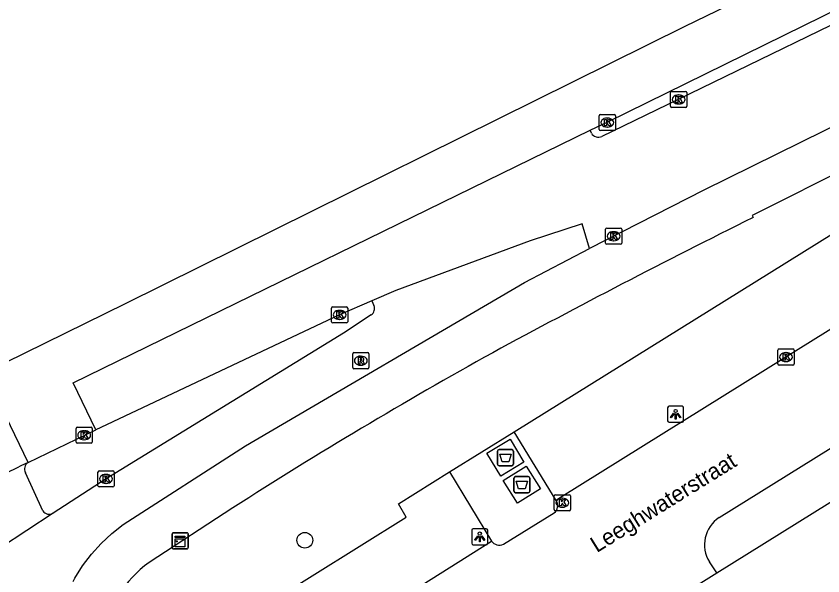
# Model space of a CAD drawing. Extents: x 159888 to 160757, y 384031 to 384746.
# Drawn here: x 160015.4 to 160065.5, y 384569.7 to 384604.4 of the extents above; entities that cross this region are included whole.
import ezdxf

# ---------------------------------------------------------------- set-up
doc = ezdxf.new("R2010")
doc.units = 0
for name, color, linetype in [('IMGEO_Afval_apart_plaats', 7, 'Continuous'), ('IMGEO_Boom', 7, 'Continuous'), ('IMGEO_Fietspad_gesloten', 7, 'Continuous'), ('IMGEO_Kast', 7, 'Continuous'), ('IMGEO_Kolk', 7, 'Continuous'), ('IMGEO_Lichtpunt', 7, 'Continuous'), ('IMGEO_Openbare_ruimte_label', 7, 'Continuous'), ('IMGEO_Pand', 7, 'Continuous'), ('IMGEO_Parkeervlak_open', 7, 'Continuous'), ('IMGEO_Rijbaan_lokaal_open', 7, 'Continuous'), ('IMGEO_Rijbaan_regionaal_gesloten', 7, 'Continuous'), ('IMGEO_Rioolput', 7, 'Continuous'), ('IMGEO_Voetpad_gesloten', 7, 'Continuous'), ('IMGEO_Voetpad_open', 7, 'Continuous')]:
    doc.layers.add(name, color=color, linetype=linetype)

msp = doc.modelspace()

# ---------------------------------------------------------------- linework, layer by layer
at = {"layer": 'IMGEO_Afval_apart_plaats'}
for p, q in [((160045.285, 384576.603), (160045.285, 384577.403)), ((160045.285, 384577.403), (160045.285, 384576.603)), ((160045.385, 384577.503), (160046.175, 384577.503)), ((160046.175, 384577.503), (160045.385, 384577.503)), ((160046.275, 384577.403), (160046.275, 384576.603)), ((160046.275, 384576.603), (160046.275, 384577.403)), ((160046.175, 384576.503), (160045.385, 384576.503)), ((160045.385, 384576.503), (160046.175, 384576.503)), ((160046.309, 384574.927), (160046.309, 384575.727)), ((160046.309, 384575.727), (160046.309, 384574.927)), ((160046.409, 384575.827), (160047.199, 384575.827)), ((160047.199, 384575.827), (160046.409, 384575.827)), ((160047.299, 384575.727), (160047.299, 384574.927)), ((160047.299, 384574.927), (160047.299, 384575.727)), ((160047.199, 384574.827), (160046.409, 384574.827)), ((160046.409, 384574.827), (160047.199, 384574.827))]:
    msp.add_line(p, q, dxfattribs=at)
for points in [[(160045.428, 384577.217), (160046.132, 384577.217), (160045.983, 384576.747), (160045.577, 384576.747), (160045.428, 384577.217)], [(160046.452, 384575.541), (160047.156, 384575.541), (160047.007, 384575.071), (160046.601, 384575.071), (160046.452, 384575.541)]]:
    msp.add_lwpolyline(points, dxfattribs=at)
for centre, start, end in [((160045.385, 384577.403), 90, 180), ((160045.385, 384577.403), 90, 180), ((160046.175, 384577.403), 0, 90), ((160046.175, 384577.403), 360, 90), ((160045.385, 384576.603), 180, 270), ((160045.385, 384576.603), 180, 270), ((160046.175, 384576.603), 270, 0), ((160046.175, 384576.603), 270, 0), ((160046.409, 384575.727), 90, 180), ((160046.409, 384575.727), 90, 180), ((160047.199, 384575.727), 0, 90), ((160047.199, 384575.727), 360, 90), ((160046.409, 384574.927), 180, 270), ((160046.409, 384574.927), 180, 270), ((160047.199, 384574.927), 270, 0), ((160047.199, 384574.927), 270, 0)]:
    msp.add_arc(centre, 0.1, start, end, dxfattribs=at)
at = {"layer": 'IMGEO_Boom'}
msp.add_circle((160033.317, 384571.876), 0.489, dxfattribs=at)
at = {"layer": 'IMGEO_Fietspad_gesloten'}
for points in [[(160018.927, 384569.315), (160019.03, 384569.518), (160019.508, 384570.287), (160020.053, 384571.009), (160020.659, 384571.68), (160021.324, 384572.294), (160022.04, 384572.846), (160029.623, 384577.749), (160046.967, 384587.883), (160051.012, 384589.991)], [(160037.477, 384586.735), (160037.608, 384586.46)], [(160037.444, 384585.867), (160035.722, 384584.738), (160020.966, 384575.687), (160017.679, 384573.562)], [(160017.679, 384573.562), (160014.403, 384571.399)]]:
    msp.add_lwpolyline(points, dxfattribs=at)
msp.add_arc((160037.168, 384586.262), 0.482, 304.8999, 24.1814, dxfattribs=at)
at = {"layer": 'IMGEO_Kast'}
for p, q in [((160025.07, 384571.421), (160025.07, 384572.262)), ((160025.07, 384572.262), (160025.07, 384571.421)), ((160025.145, 384572.346), (160025.986, 384572.346)), ((160025.986, 384572.346), (160025.145, 384572.346)), ((160026.07, 384572.271), (160026.07, 384571.43)), ((160026.07, 384571.43), (160026.07, 384572.271)), ((160025.995, 384571.346), (160025.154, 384571.346)), ((160025.154, 384571.346), (160025.995, 384571.346))]:
    msp.add_line(p, q, dxfattribs=at)
for points in [[(160025.265, 384572.136), (160025.865, 384572.136), (160025.865, 384572.051), (160025.265, 384572.051), (160025.265, 384572.136)], [(160025.265, 384571.961), (160025.865, 384571.961), (160025.865, 384571.472), (160025.265, 384571.472), (160025.265, 384571.961)]]:
    msp.add_lwpolyline(points, dxfattribs=at)
msp.add_circle((160025.349, 384571.81), 0.0377, dxfattribs=at)
for centre, start, end in [((160025.148, 384572.268), 92.4484, 184.2845), ((160025.148, 384572.268), 92.4484, 184.2845), ((160025.992, 384572.268), 2.4484, 94.2845), ((160025.992, 384572.268), 2.4484, 94.2845), ((160025.148, 384571.424), 182.4484, 274.2845), ((160025.148, 384571.424), 182.4484, 274.2845), ((160025.992, 384571.424), 272.4484, 4.2845), ((160025.992, 384571.424), 272.4484, 4.2845)]:
    msp.add_arc(centre, 0.0779, start, end, dxfattribs=at)
at = {"layer": 'IMGEO_Kolk'}
for p, q in [((160056.04, 384598.822), (160056.04, 384599.674)), ((160056.115, 384599.748), (160056.967, 384599.748)), ((160057.041, 384599.674), (160057.041, 384598.822)), ((160056.528, 384599.528), (160056.553, 384599.528)), ((160056.967, 384598.748), (160056.115, 384598.748)), ((160056.551, 384598.968), (160056.526, 384598.968)), ((160051.608, 384597.387), (160051.608, 384598.239)), ((160051.683, 384598.313), (160052.535, 384598.313)), ((160052.609, 384598.239), (160052.609, 384597.387)), ((160052.096, 384598.093), (160052.121, 384598.093)), ((160052.535, 384597.313), (160051.683, 384597.313)), ((160052.119, 384597.533), (160052.094, 384597.533)), ((160052.002, 384590.332), (160052.002, 384591.184)), ((160052.077, 384591.258), (160052.929, 384591.258)), ((160053.003, 384591.184), (160053.003, 384590.332)), ((160052.49, 384591.038), (160052.515, 384591.038)), ((160052.929, 384590.258), (160052.077, 384590.258)), ((160052.513, 384590.478), (160052.488, 384590.478)), ((160034.977, 384585.446), (160034.977, 384586.298)), ((160035.052, 384586.372), (160035.904, 384586.372)), ((160035.465, 384586.152), (160035.49, 384586.152)), ((160035.978, 384586.298), (160035.978, 384585.446)), ((160035.488, 384585.592), (160035.463, 384585.592)), ((160035.904, 384585.372), (160035.052, 384585.372)), ((160062.709, 384582.827), (160062.709, 384583.679)), ((160062.784, 384583.753), (160063.636, 384583.753)), ((160063.71, 384583.679), (160063.71, 384582.827)), ((160063.197, 384583.533), (160063.222, 384583.533)), ((160063.636, 384582.753), (160062.784, 384582.753)), ((160063.22, 384582.973), (160063.195, 384582.973)), ((160019.106, 384577.974), (160019.106, 384578.826)), ((160019.181, 384578.9), (160020.033, 384578.9)), ((160019.594, 384578.68), (160019.619, 384578.68)), ((160020.107, 384578.826), (160020.107, 384577.974)), ((160019.617, 384578.12), (160019.592, 384578.12)), ((160020.033, 384577.9), (160019.181, 384577.9)), ((160020.465, 384575.261), (160020.465, 384576.113)), ((160020.54, 384576.187), (160021.392, 384576.187)), ((160021.466, 384576.113), (160021.466, 384575.261)), ((160020.953, 384575.967), (160020.978, 384575.967)), ((160021.392, 384575.187), (160020.54, 384575.187)), ((160020.976, 384575.407), (160020.951, 384575.407)), ((160048.813, 384573.78), (160048.813, 384574.632)), ((160048.888, 384574.706), (160049.74, 384574.706)), ((160049.814, 384574.632), (160049.814, 384573.78)), ((160049.301, 384574.486), (160049.326, 384574.486)), ((160049.74, 384573.706), (160048.888, 384573.706)), ((160049.324, 384573.926), (160049.299, 384573.926))]:
    msp.add_line(p, q, dxfattribs=at)
for points in [[(160056.04, 384598.822), (160056.04, 384599.674)], [(160056.115, 384599.748), (160056.967, 384599.748)], [(160057.041, 384599.674), (160057.041, 384598.822)], [(160056.361, 384599.448), (160056.484, 384599.448), (160056.484, 384599.297), (160056.614, 384599.448), (160056.778, 384599.448), (160056.632, 384599.297), (160056.785, 384599.048), (160056.633, 384599.048), (160056.548, 384599.212), (160056.484, 384599.145), (160056.484, 384599.048), (160056.361, 384599.048), (160056.361, 384599.448)], [(160056.967, 384598.748), (160056.115, 384598.748)], [(160051.608, 384597.387), (160051.608, 384598.239)], [(160051.683, 384598.313), (160052.535, 384598.313)], [(160052.609, 384598.239), (160052.609, 384597.387)], [(160051.929, 384598.013), (160052.052, 384598.013), (160052.052, 384597.862), (160052.182, 384598.013), (160052.346, 384598.013), (160052.2, 384597.862), (160052.353, 384597.613), (160052.201, 384597.613), (160052.116, 384597.777), (160052.052, 384597.71), (160052.052, 384597.613), (160051.929, 384597.613), (160051.929, 384598.013)], [(160052.535, 384597.313), (160051.683, 384597.313)], [(160052.002, 384590.332), (160052.002, 384591.184)], [(160052.077, 384591.258), (160052.929, 384591.258)], [(160053.003, 384591.184), (160053.003, 384590.332)], [(160052.323, 384590.958), (160052.446, 384590.958), (160052.446, 384590.807), (160052.576, 384590.958), (160052.74, 384590.958), (160052.594, 384590.807), (160052.747, 384590.558), (160052.595, 384590.558), (160052.51, 384590.722), (160052.446, 384590.655), (160052.446, 384590.558), (160052.323, 384590.558), (160052.323, 384590.958)], [(160052.929, 384590.258), (160052.077, 384590.258)], [(160034.977, 384585.446), (160034.977, 384586.298)], [(160035.052, 384586.372), (160035.904, 384586.372)], [(160035.978, 384586.298), (160035.978, 384585.446)], [(160035.298, 384586.072), (160035.421, 384586.072), (160035.421, 384585.921), (160035.551, 384586.072), (160035.715, 384586.072), (160035.569, 384585.921), (160035.722, 384585.672), (160035.57, 384585.672), (160035.485, 384585.836), (160035.421, 384585.769), (160035.421, 384585.672), (160035.298, 384585.672), (160035.298, 384586.072)], [(160035.904, 384585.372), (160035.052, 384585.372)], [(160062.709, 384582.827), (160062.709, 384583.679)], [(160062.784, 384583.753), (160063.636, 384583.753)], [(160063.71, 384583.679), (160063.71, 384582.827)], [(160063.03, 384583.453), (160063.153, 384583.453), (160063.153, 384583.302), (160063.283, 384583.453), (160063.447, 384583.453), (160063.301, 384583.302), (160063.454, 384583.053), (160063.302, 384583.053), (160063.217, 384583.217), (160063.153, 384583.15), (160063.153, 384583.053), (160063.03, 384583.053), (160063.03, 384583.453)], [(160063.636, 384582.753), (160062.784, 384582.753)], [(160019.106, 384577.974), (160019.106, 384578.826)], [(160019.181, 384578.9), (160020.033, 384578.9)], [(160019.427, 384578.6), (160019.55, 384578.6), (160019.55, 384578.449), (160019.68, 384578.6), (160019.844, 384578.6), (160019.698, 384578.449), (160019.851, 384578.2), (160019.699, 384578.2), (160019.614, 384578.364), (160019.55, 384578.297), (160019.55, 384578.2), (160019.427, 384578.2), (160019.427, 384578.6)], [(160020.107, 384578.826), (160020.107, 384577.974)], [(160020.033, 384577.9), (160019.181, 384577.9)], [(160020.465, 384575.261), (160020.465, 384576.113)], [(160020.54, 384576.187), (160021.392, 384576.187)], [(160021.466, 384576.113), (160021.466, 384575.261)], [(160020.786, 384575.887), (160020.909, 384575.887), (160020.909, 384575.736), (160021.039, 384575.887), (160021.203, 384575.887), (160021.057, 384575.736), (160021.21, 384575.487), (160021.058, 384575.487), (160020.973, 384575.651), (160020.909, 384575.584), (160020.909, 384575.487), (160020.786, 384575.487), (160020.786, 384575.887)], [(160021.392, 384575.187), (160020.54, 384575.187)], [(160048.813, 384573.78), (160048.813, 384574.632)], [(160048.888, 384574.706), (160049.74, 384574.706)], [(160049.814, 384574.632), (160049.814, 384573.78)], [(160049.134, 384574.406), (160049.257, 384574.406), (160049.257, 384574.255), (160049.387, 384574.406), (160049.551, 384574.406), (160049.405, 384574.255), (160049.558, 384574.006), (160049.406, 384574.006), (160049.321, 384574.17), (160049.257, 384574.103), (160049.257, 384574.006), (160049.134, 384574.006), (160049.134, 384574.406)], [(160049.74, 384573.706), (160048.888, 384573.706)]]:
    msp.add_lwpolyline(points, dxfattribs=at)
for centre, start, end in [((160056.117, 384599.672), 91.552, 178.448), ((160056.117, 384599.672), 91.552, 178.448), ((160056.965, 384599.672), 1.552, 88.448), ((160056.965, 384599.672), 1.552, 88.448), ((160056.117, 384598.824), 181.552, 268.448), ((160056.117, 384598.824), 181.552, 268.448), ((160056.965, 384598.824), 271.552, 358.448), ((160056.965, 384598.824), 271.552, 358.448), ((160051.685, 384598.237), 91.552, 178.448), ((160051.685, 384598.237), 91.552, 178.448), ((160052.533, 384598.237), 1.552, 88.448), ((160052.533, 384598.237), 1.552, 88.448), ((160051.685, 384597.389), 181.552, 268.448), ((160051.685, 384597.389), 181.552, 268.448), ((160052.533, 384597.389), 271.552, 358.448), ((160052.533, 384597.389), 271.552, 358.448), ((160052.079, 384591.182), 91.552, 178.448), ((160052.079, 384591.182), 91.552, 178.448), ((160052.927, 384591.182), 1.552, 88.448), ((160052.927, 384591.182), 1.552, 88.448), ((160052.079, 384590.334), 181.552, 268.448), ((160052.079, 384590.334), 181.552, 268.448), ((160052.927, 384590.334), 271.552, 358.448), ((160052.927, 384590.334), 271.552, 358.448), ((160035.054, 384586.296), 91.552, 178.448), ((160035.054, 384586.296), 91.552, 178.448), ((160035.902, 384586.296), 1.552, 88.448), ((160035.902, 384586.296), 1.552, 88.448), ((160035.054, 384585.448), 181.552, 268.448), ((160035.054, 384585.448), 181.552, 268.448), ((160035.902, 384585.448), 271.552, 358.448), ((160035.902, 384585.448), 271.552, 358.448), ((160062.786, 384583.677), 91.552, 178.448), ((160062.786, 384583.677), 91.552, 178.448), ((160063.634, 384583.677), 1.552, 88.448), ((160063.634, 384583.677), 1.552, 88.448), ((160062.786, 384582.829), 181.552, 268.448), ((160062.786, 384582.829), 181.552, 268.448), ((160063.634, 384582.829), 271.552, 358.448), ((160063.634, 384582.829), 271.552, 358.448), ((160019.183, 384578.824), 91.552, 178.448), ((160019.183, 384578.824), 91.552, 178.448), ((160020.031, 384578.824), 1.552, 88.448), ((160020.031, 384578.824), 1.552, 88.448), ((160019.183, 384577.976), 181.552, 268.448), ((160019.183, 384577.976), 181.552, 268.448), ((160020.031, 384577.976), 271.552, 358.448), ((160020.031, 384577.976), 271.552, 358.448), ((160020.542, 384576.111), 91.552, 178.448), ((160020.542, 384576.111), 91.552, 178.448), ((160021.39, 384576.111), 1.552, 88.448), ((160021.39, 384576.111), 1.552, 88.448), ((160020.542, 384575.263), 181.552, 268.448), ((160020.542, 384575.263), 181.552, 268.448), ((160021.39, 384575.263), 271.552, 358.448), ((160021.39, 384575.263), 271.552, 358.448), ((160048.89, 384574.63), 91.552, 178.448), ((160048.89, 384574.63), 91.552, 178.448), ((160049.738, 384574.63), 1.552, 88.448), ((160049.738, 384574.63), 1.552, 88.448), ((160048.89, 384573.782), 181.552, 268.448), ((160048.89, 384573.782), 181.552, 268.448), ((160049.738, 384573.782), 271.552, 358.448), ((160049.738, 384573.782), 271.552, 358.448)]:
    msp.add_arc(centre, 0.0765, start, end, dxfattribs=at)
for centre, major_axis, ratio, start_param, end_param in [((160056.527, 384599.248), (-0.387, 0.002), 0.722429, 4.712389, 7.853982), ((160056.552, 384599.248), (-0.39, 0.002), 0.717154, 1.570796, 4.712389), ((160052.095, 384597.813), (-0.387, 0.002), 0.722429, 4.712389, 7.853982), ((160052.12, 384597.813), (-0.39, 0.002), 0.717154, 1.570796, 4.712389), ((160052.489, 384590.758), (-0.387, 0.002), 0.722429, 4.712389, 7.853982), ((160052.514, 384590.758), (-0.39, 0.002), 0.717154, 1.570796, 4.712389), ((160035.464, 384585.872), (-0.387, 0.002), 0.722429, 4.712389, 7.853982), ((160035.489, 384585.872), (-0.39, 0.002), 0.717154, 1.570796, 4.712389), ((160063.196, 384583.253), (-0.387, 0.002), 0.722429, 4.712389, 7.853982), ((160063.221, 384583.253), (-0.39, 0.002), 0.717154, 1.570796, 4.712389), ((160019.593, 384578.4), (-0.387, 0.002), 0.722429, 4.712389, 7.853982), ((160019.618, 384578.4), (-0.39, 0.002), 0.717154, 1.570796, 4.712389), ((160020.952, 384575.687), (-0.387, 0.002), 0.722429, 4.712389, 7.853982), ((160020.977, 384575.687), (-0.39, 0.002), 0.717154, 1.570796, 4.712389), ((160049.3, 384574.206), (-0.387, 0.002), 0.722429, 4.712389, 7.853982), ((160049.325, 384574.206), (-0.39, 0.002), 0.717154, 1.570796, 4.712389)]:
    msp.add_ellipse(centre, major_axis=major_axis, ratio=ratio, start_param=start_param, end_param=end_param, dxfattribs=at)
at = {"layer": 'IMGEO_Lichtpunt'}
for p, q in [((160055.856, 384580.101), (160055.856, 384579.294)), ((160055.856, 384580.101), (160055.856, 384579.294)), ((160056.758, 384580.196), (160055.95, 384580.196)), ((160056.758, 384580.196), (160055.95, 384580.196)), ((160056.852, 384579.294), (160056.852, 384580.101)), ((160056.852, 384579.294), (160056.852, 384580.101)), ((160055.95, 384579.2), (160056.758, 384579.2)), ((160055.95, 384579.2), (160056.758, 384579.2)), ((160044.586, 384572.588), (160043.778, 384572.588)), ((160044.586, 384572.588), (160043.778, 384572.588)), ((160043.684, 384572.493), (160043.684, 384571.686)), ((160043.684, 384572.493), (160043.684, 384571.686)), ((160044.68, 384571.686), (160044.68, 384572.493)), ((160044.68, 384571.686), (160044.68, 384572.493)), ((160043.778, 384571.592), (160044.586, 384571.592)), ((160043.778, 384571.592), (160044.586, 384571.592))]:
    msp.add_line(p, q, dxfattribs=at)
for points in [[(160056.23, 384579.765), (160056.269, 384579.737), (160056.081, 384579.475), (160056.043, 384579.502), (160056.23, 384579.765)], [(160056.332, 384579.717), (160056.379, 384579.717), (160056.379, 384579.395), (160056.332, 384579.395), (160056.332, 384579.717)], [(160056.442, 384579.737), (160056.48, 384579.764), (160056.667, 384579.502), (160056.628, 384579.474), (160056.442, 384579.737)], [(160044.058, 384572.157), (160044.097, 384572.129), (160043.909, 384571.867), (160043.871, 384571.894), (160044.058, 384572.157)], [(160044.16, 384572.109), (160044.207, 384572.109), (160044.207, 384571.787), (160044.16, 384571.787), (160044.16, 384572.109)], [(160044.27, 384572.129), (160044.308, 384572.156), (160044.495, 384571.894), (160044.456, 384571.866), (160044.27, 384572.129)]]:
    msp.add_lwpolyline(points, dxfattribs=at)
for centre in [(160056.355, 384579.899), (160044.183, 384572.291)]:
    msp.add_circle(centre, 0.0994, dxfattribs=at)
for centre, start, end in [((160055.95, 384580.101), 90, 180), ((160055.95, 384580.101), 90, 180), ((160056.758, 384580.101), 0, 90), ((160056.758, 384580.101), 0, 90), ((160055.95, 384579.294), 180, 270), ((160055.95, 384579.294), 180, 270), ((160056.758, 384579.294), 270, 0), ((160056.758, 384579.294), 270, 360), ((160043.778, 384572.493), 90, 180), ((160043.778, 384572.493), 90, 180), ((160044.586, 384572.493), 0, 90), ((160044.586, 384572.493), 0, 90), ((160043.778, 384571.686), 180, 270), ((160043.778, 384571.686), 180, 270), ((160044.586, 384571.686), 270, 0), ((160044.586, 384571.686), 270, 360)]:
    msp.add_arc(centre, 0.0946, start, end, dxfattribs=at)
at = {"layer": 'IMGEO_Pand'}
for points in [[(160058.915, 384569.852), (160087.761, 384587.808)], [(160056.098, 384568.098), (160058.915, 384569.852)]]:
    msp.add_lwpolyline(points, dxfattribs=at)
at = {"layer": 'IMGEO_Parkeervlak_open'}
for points in [[(160046.319, 384578.614), (160080.21, 384599.684)], [(160030.322, 384562.19), (160027.94, 384566.017), (160039.617, 384573.313), (160039.13, 384574.145), (160042.305, 384576.119)]]:
    msp.add_lwpolyline(points, dxfattribs=at)
at = {"layer": 'IMGEO_Rijbaan_lokaal_open'}
for points in [[(160072.085, 384606.834), (160071.68, 384606.642), (160070.314, 384605.978), (160056.508, 384599.25), (160051.773, 384596.955)], [(160074.57, 384601.665), (160074.153, 384601.473), (160070.11, 384599.533), (160058.105, 384593.605), (160051.012, 384589.991)], [(160051.122, 384597.159), (160051.034, 384597.347)], [(160082.837, 384595.45), (160076.899, 384591.751), (160063.21, 384583.254), (160049.139, 384574.485), (160048.923, 384574.349)], [(160051.012, 384589.991), (160050.544, 384591.519), (160047.306, 384590.469), (160038.966, 384587.378), (160037.477, 384586.735)], [(160059.065, 384573.296), (160086.219, 384590.183), (160086.266, 384590.212)], [(160037.477, 384586.735), (160035.478, 384585.873), (160020.644, 384578.882), (160020.333, 384578.732)], [(160045.651, 384571.63), (160048.799, 384573.571)], [(160030.322, 384562.19), (160035.343, 384565.788), (160044.922, 384571.827)], [(160058.915, 384569.852), (160058.454, 384570.529)]]:
    msp.add_lwpolyline(points, dxfattribs=at)
for centre, radius, start, end in [((160051.558, 384597.411), 0.504, 209.9984, 295.2034), ((160048.475, 384574.022), 0.555, 305.7184, 36.17), ((160060.187, 384571.597), 2.036, 123.4431, 211.6528), ((160045.4, 384572.147), 0.575, 213.8444, 295.9115)]:
    msp.add_arc(centre, radius, start, end, dxfattribs=at)
at = {"layer": 'IMGEO_Rijbaan_regionaal_gesloten'}
for points in [[(160013.443, 384582.29), (160022.181, 384586.577), (160056.938, 384603.792), (160124.235, 384636.399), (160172.896, 384659.514), (160176.646, 384661.295), (160199.533, 384671.786), (160241.721, 384691.124)], [(160051.034, 384597.347), (160052.142, 384597.867), (160067.94, 384605.632), (160083.713, 384613.363), (160099.478, 384621.101), (160100.406, 384621.559), (160109.527, 384625.978), (160118.928, 384630.438), (160138.462, 384639.606), (160158.014, 384648.764), (160177.522, 384657.939), (160178.098, 384658.209), (160197.066, 384667.108), (160205.886, 384671.287)], [(160020.333, 384578.732), (160018.929, 384581.642), (160051.034, 384597.347)], [(160016.118, 384576.695), (160014.762, 384579.531), (160014.756, 384579.543), (160013.443, 384582.29)], [(160016.118, 384576.695), (160020.333, 384578.732)]]:
    msp.add_lwpolyline(points, dxfattribs=at)
msp.add_arc((160029.145, 384548.177), 31.353, 114.5511, 121.7177, dxfattribs=at)
at = {"layer": 'IMGEO_Rioolput'}
for p, q in [((160036.293, 384582.601), (160036.293, 384583.453)), ((160036.368, 384583.527), (160037.22, 384583.527)), ((160036.781, 384583.307), (160036.806, 384583.307)), ((160037.294, 384583.453), (160037.294, 384582.601)), ((160036.804, 384582.747), (160036.779, 384582.747)), ((160037.22, 384582.527), (160036.368, 384582.527))]:
    msp.add_line(p, q, dxfattribs=at)
for points in [[(160036.293, 384582.601), (160036.293, 384583.453)], [(160036.368, 384583.527), (160037.22, 384583.527)], [(160036.882, 384583.225), (160036.63, 384583.227), (160036.63, 384582.827)], [(160036.808, 384583.146), (160036.754, 384583.146), (160036.754, 384583.065)], [(160037.294, 384583.453), (160037.294, 384582.601)], [(160036.63, 384582.827), (160036.754, 384582.827), (160036.754, 384582.989), (160036.765, 384582.989)], [(160036.754, 384583.065), (160036.806, 384583.065)], [(160036.812, 384582.96), (160036.883, 384582.827), (160037.023, 384582.827), (160036.958, 384582.953)], [(160037.22, 384582.527), (160036.368, 384582.527)]]:
    msp.add_lwpolyline(points, dxfattribs=at)
for centre, radius, start, end in [((160036.37, 384583.451), 0.0765, 91.552, 178.448), ((160036.37, 384583.451), 0.0765, 91.552, 178.448), ((160036.814, 384583.05), 0.0964, 77.0061, 93.1865), ((160036.828, 384583.107), 0.0378, 276.6634, 79.6772), ((160036.881, 384583.115), 0.109, 350.3612, 89.416), ((160036.879, 384583.115), 0.112, 277.5842, 350.9817), ((160037.218, 384583.451), 0.0765, 1.552, 88.448), ((160037.218, 384583.451), 0.0765, 1.552, 88.448), ((160036.37, 384582.603), 0.0765, 181.552, 268.448), ((160036.37, 384582.603), 0.0765, 181.552, 268.448), ((160036.764, 384582.936), 0.0533, 26.0293, 88.6989), ((160036.79, 384583.254), 0.19, 274.7715, 282.9687), ((160036.863, 384582.9), 0.108, 29.5134, 73.7905), ((160037.218, 384582.603), 0.0765, 271.552, 358.448), ((160037.218, 384582.603), 0.0765, 271.552, 358.448)]:
    msp.add_arc(centre, radius, start, end, dxfattribs=at)
for centre, major_axis, ratio, start_param, end_param in [((160036.78, 384583.027), (-0.387, 0.002), 0.722429, 4.712389, 7.853982), ((160036.805, 384583.027), (-0.39, 0.002), 0.717154, 1.570796, 4.712389)]:
    msp.add_ellipse(centre, major_axis=major_axis, ratio=ratio, start_param=start_param, end_param=end_param, dxfattribs=at)
at = {"layer": 'IMGEO_Voetpad_gesloten'}
for points in [[(160045.493, 384575.852), (160044.628, 384577.287), (160046.067, 384578.155), (160046.932, 384576.72), (160045.493, 384575.852)], [(160046.533, 384574.173), (160045.646, 384575.583), (160047.074, 384576.482), (160047.962, 384575.072), (160046.533, 384574.173)]]:
    msp.add_lwpolyline(points, dxfattribs=at)
at = {"layer": 'IMGEO_Voetpad_open'}
for points in [[(160080.324, 384599.771), (160079.561, 384600.984), (160067.469, 384595.226), (160061.105, 384592.035), (160061.164, 384591.917)], [(160042.305, 384576.119), (160046.319, 384578.614)], [(160048.923, 384574.349), (160046.319, 384578.614)], [(160017.038, 384573.696), (160015.961, 384576.073)], [(160042.305, 384576.119), (160044.922, 384571.827)], [(160028.848, 384573.887), (160023.645, 384570.503)]]:
    msp.add_lwpolyline(points, dxfattribs=at)
for centre, radius, start, end in [((160293.123, 384125.251), 521.136, 116.42991, 118.43302), ((160187.225, 384326.884), 293.417, 118.99536, 122.66773), ((160016.362, 384576.303), 0.462, 121.8577, 209.8098), ((160017.43, 384573.972), 0.479, 215.1175, 301.2674), ((160028.007, 384564.513), 7.41, 126.0664, 169.569)]:
    msp.add_arc(centre, radius, start, end, dxfattribs=at)

# ---------------------------------------------------------------- texts
at = {"layer": 'IMGEO_Openbare_ruimte_label'}
msp.add_text('Leeghwaterstraat', height=1, rotation=31.8778, dxfattribs=at).set_placement((160051.457, 384571.077))

doc.saveas('drawing.dxf')
